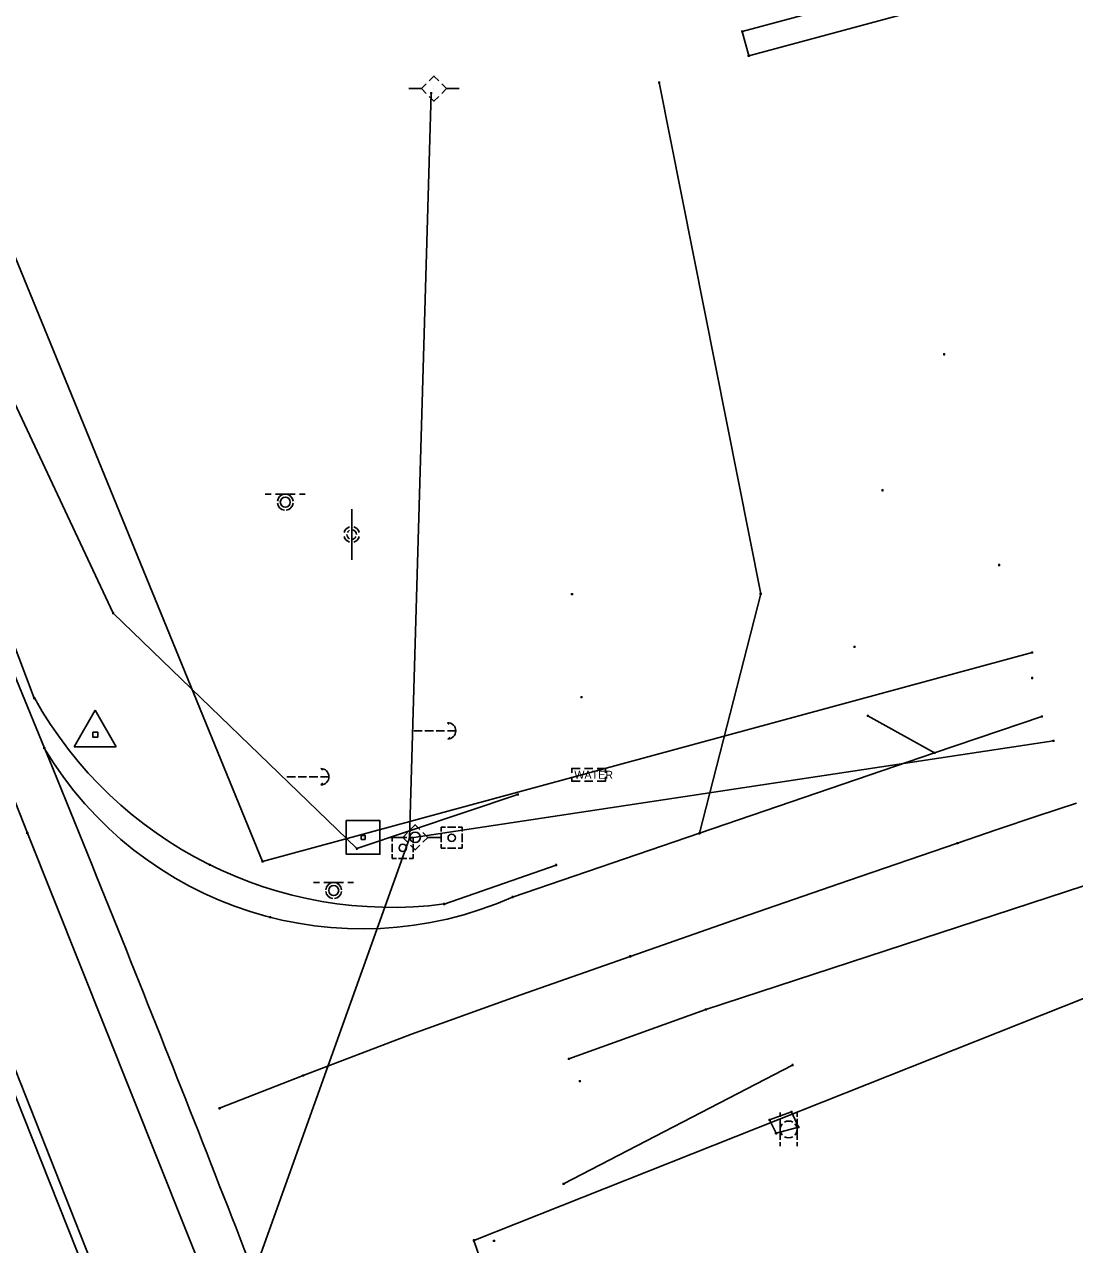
# Model space of a CAD drawing. Extents: x 1954856 to 2011933, y 399149 to 426294.
# Drawn here: x 2004670.5 to 2004795.1, y 408666 to 408810.8 of the extents above; entities that cross this region are included whole.
import ezdxf

# ---------------------------------------------------------------- set-up
doc = ezdxf.new("R2010")
doc.units = 0
for name, color, linetype in [('BankMent_ep', 7, 'Continuous'), ('BaselineSurvey', 7, 'Continuous'), ('DelineatorPost_ep', 7, 'Continuous'), ('Driveway_ep', 7, 'Continuous'), ('ElecAer_ep', 7, 'Continuous'), ('GuyWireAnchor_ep', 7, 'Continuous'), ('MeterWater_ep', 7, 'Continuous'), ('MonumentCC_ep', 7, 'Continuous'), ('MonumentNL_ep', 7, 'Continuous'), ('PavtAsphalt_ep', 7, 'Continuous'), ('PavtAsphaltCrown_ep', 7, 'Continuous'), ('PointLocator_ep', 7, 'Continuous'), ('PoleElec_ep', 7, 'Continuous'), ('PoleShared_ep', 7, 'Continuous'), ('ShldrPaved_ep', 7, 'Continuous'), ('SidewalkFront_ep', 7, 'Continuous'), ('SignSingle_ep', 7, 'Continuous'), ('TelePed_ep', 7, 'Continuous'), ('TeleServBox_ep', 7, 'Continuous'), ('TreeLineScatter_ep', 7, 'Continuous'), ('TreeLineWoods_ep', 7, 'Continuous'), ('WaterFct_ep', 7, 'Continuous')]:
    doc.layers.add(name, color=color, linetype=linetype)

msp = doc.modelspace()

# ---------------------------------------------------------------- linework, layer by layer
at = {"layer": 'BankMent_ep'}
for p, q in [((2004671.65, 408730.86), (2004641.52, 408810.02)), ((2004681, 408740.93), (2004663.38, 408778.51)), ((2004709.94, 408712.99), (2004681, 408740.93)), ((2004729.03, 408719.41), (2004709.94, 408712.99)), ((2004733.59, 408711.03), (2004720.32, 408706.41)), ((2004734.48, 408673.19), (2004761.65, 408687.3))]:
    msp.add_line(p, q, dxfattribs=at)
msp.add_arc((2004714.07, 408754.62), 48.61, 209.2548, 277.3919, dxfattribs=at)
at = {"layer": 'BaselineSurvey'}
msp.add_line((2004967.71, 407935.04), (2004043.6, 410254.04), dxfattribs=at)
msp.add_line((2004967.71, 407935.04), (2004043.6, 410254.04), dxfattribs=at)
at = {"layer": 'DelineatorPost_ep'}
for p, q in [((2004760.19, 408681.65), (2004760.19, 408681.15)), ((2004760.19, 408678.4), (2004760.19, 408680.9)), ((2004762.19, 408681.65), (2004762.19, 408681.15)), ((2004762.19, 408680.9), (2004762.19, 408678.4)), ((2004761.19, 408679.65), (2004761.19, 408679.65)), ((2004760.19, 408678.15), (2004760.19, 408677.65)), ((2004762.19, 408678.15), (2004762.19, 408677.65))]:
    msp.add_line(p, q, dxfattribs=at)
for start, end in [(60, 120), (138.5904, 221.4096), (318.5904, 41.4096), (240, 300)]:
    msp.add_arc((2004761.19, 408679.65), 1, start, end, dxfattribs=at)
at = {"layer": 'Driveway_ep'}
msp.add_line((2004778.5, 408724.36), (2004770.59, 408728.75), dxfattribs=at)
msp.add_lwpolyline([(2004750.63, 408714.8), (2004757.88, 408743.22), (2004745.83, 408803.92)], dxfattribs=at)
at = {"layer": 'ElecAer_ep'}
for points in [[(2004716.19, 408714.22), (2004718.76, 408802.67)], [(2004669.71, 408584.23), (2004716.19, 408714.22), (2004792.62, 408725.78)]]:
    msp.add_lwpolyline(points, dxfattribs=at)
at = {"layer": 'GuyWireAnchor_ep'}
for p, q in [((2004716.69, 408726.97), (2004717.69, 408726.97)), ((2004718.02, 408726.97), (2004719.02, 408726.97)), ((2004719.35, 408726.97), (2004720.35, 408726.97)), ((2004720.71, 408727.93), (2004720.91, 408727.74)), ((2004720.69, 408726.96), (2004721.69, 408726.96)), ((2004720.73, 408725.99), (2004720.97, 408726.22)), ((2004721.69, 408726.96), (2004721.69, 408726.96)), ((2004701.64, 408721.52), (2004702.64, 408721.52)), ((2004702.97, 408721.52), (2004703.97, 408721.52)), ((2004704.3, 408721.52), (2004705.3, 408721.52)), ((2004705.64, 408721.51), (2004706.64, 408721.51)), ((2004705.66, 408722.48), (2004705.86, 408722.29)), ((2004706.64, 408721.51), (2004706.64, 408721.51)), ((2004705.68, 408720.54), (2004705.92, 408720.77))]:
    msp.add_line(p, q, dxfattribs=at)
for centre in [(2004720.71, 408726.96), (2004705.66, 408721.51)]:
    msp.add_arc(centre, 0.973, 271.14, 90.0059, dxfattribs=at)
at = {"layer": 'MeterWater_ep'}
msp.add_line((2004737.45, 408721.74), (2004737.45, 408721.74), dxfattribs=at)
for points in [[(2004735.45, 408721.99), (2004735.45, 408722.5), (2004736.45, 408722.5)], [(2004736.45, 408720.99), (2004735.45, 408720.99), (2004735.45, 408721.49)], [(2004736.95, 408722.5), (2004737.95, 408722.5)], [(2004738.45, 408722.5), (2004739.45, 408722.5), (2004739.45, 408721.99)], [(2004739.45, 408721.49), (2004739.45, 408720.99), (2004738.45, 408720.99)], [(2004737.95, 408720.99), (2004736.95, 408720.99)]]:
    msp.add_lwpolyline(points, dxfattribs=at)
at = {"layer": 'MonumentCC_ep'}
msp.add_line((2004710.68, 408714.32), (2004710.68, 408714.32), dxfattribs=at)
msp.add_lwpolyline([(2004708.68, 408712.32), (2004712.68, 408712.32), (2004712.68, 408716.32), (2004708.68, 408716.32), (2004708.68, 408712.32)], dxfattribs=at)
msp.add_lwpolyline([(2004710.44, 408714.08), (2004710.44, 408714.55), (2004710.92, 408714.55), (2004710.92, 408714.08)], close=True, dxfattribs=at)
at = {"layer": 'MonumentNL_ep'}
for p, q in [((2004676.39, 408725.08), (2004678.89, 408729.41)), ((2004678.89, 408729.41), (2004681.39, 408725.08)), ((2004678.89, 408726.52), (2004678.89, 408726.52)), ((2004676.39, 408725.08), (2004681.39, 408725.08))]:
    msp.add_line(p, q, dxfattribs=at)
msp.add_lwpolyline([(2004678.59, 408726.82), (2004679.19, 408726.82), (2004679.19, 408726.22), (2004678.59, 408726.22)], close=True, dxfattribs=at)
at = {"layer": 'PavtAsphalt_ep'}
for p, q in [((2004791.24, 408728.67), (2004778.5, 408724.36)), ((2004778.5, 408724.36), (2004750.63, 408714.8)), ((2004750.63, 408714.8), (2004728.42, 408707.24)), ((2004751.37, 408693.88), (2004798.39, 408709.27)), ((2004735.11, 408688.04), (2004751.37, 408693.88))]:
    msp.add_line(p, q, dxfattribs=at)
msp.add_lwpolyline([(2004930.29, 408065.1), (2004893.54, 408157.67), (2004856.38, 408250.56), (2004819.21, 408343.48), (2004782.13, 408435.87), (2004745.09, 408528.98), (2004708.04, 408621.61), (2004670.84, 408714.83), (2004634.43, 408807.2), (2004597.18, 408900.11), (2004560.23, 408993.39), (2004523.08, 409086.65), (2004486.25, 409179.55), (2004449.35, 409272.32), (2004412.41, 409364.96), (2004375.27, 409458.2), (2004338.19, 409550.48), (2004300.95, 409644.08)], dxfattribs=at)
msp.add_arc((2004710.6, 408747.41), 43.95, 210.7909, 293.9313, dxfattribs=at)
at = {"layer": 'PavtAsphaltCrown_ep'}
msp.add_line((2004693.65, 408682.16), (2004703.56, 408686.05), dxfattribs=at)
for points in [[(2004919.3, 408060.52), (2004882.31, 408153.48), (2004845.12, 408246.24), (2004807.96, 408339.12), (2004770.74, 408431.91), (2004733.82, 408525.03), (2004696.73, 408617.52), (2004659.9, 408710.76), (2004622.5, 408803.47), (2004585.74, 408896.22), (2004548.97, 408989.35), (2004511.74, 409082.34), (2004474.91, 409175.32), (2004437.75, 409268.1), (2004401.04, 409361.08), (2004363.75, 409453.88), (2004326.65, 409546.7), (2004289.56, 409639.69)], [(2004703.56, 408686.05), (2004716.44, 408690.95), (2004729.4, 408695.63), (2004742.4, 408700.19), (2004755.34, 408704.71), (2004768.29, 408709.2), (2004781.25, 408713.65), (2004785.95, 408715.24), (2004790.65, 408716.82), (2004795.35, 408718.4)]]:
    msp.add_lwpolyline(points, dxfattribs=at)
at = {"layer": 'PointLocator_ep'}
for p, q in [((2004755.82, 408809.99), (2004755.57, 408809.99)), ((2004755.69, 408809.86), (2004755.69, 408810.11)), ((2004755.69, 408809.99), (2004755.69, 408809.99)), ((2004756.57, 408807.11), (2004756.32, 408807.11)), ((2004756.45, 408806.99), (2004756.45, 408807.24)), ((2004756.45, 408807.11), (2004756.45, 408807.11)), ((2004745.95, 408803.92), (2004745.7, 408803.92)), ((2004745.83, 408803.79), (2004745.83, 408804.04)), ((2004745.83, 408803.92), (2004745.83, 408803.92)), ((2004718.89, 408802.67), (2004718.64, 408802.67)), ((2004718.76, 408802.54), (2004718.76, 408802.79)), ((2004718.76, 408802.67), (2004718.76, 408802.67)), ((2004779.79, 408771.66), (2004779.54, 408771.66)), ((2004779.66, 408771.53), (2004779.66, 408771.78)), ((2004779.66, 408771.66), (2004779.66, 408771.66)), ((2004772.45, 408755.52), (2004772.2, 408755.52)), ((2004772.32, 408755.39), (2004772.32, 408755.64)), ((2004772.32, 408755.52), (2004772.32, 408755.52)), ((2004786.31, 408746.65), (2004786.06, 408746.65)), ((2004786.18, 408746.53), (2004786.18, 408746.78)), ((2004786.18, 408746.65), (2004786.18, 408746.65)), ((2004735.6, 408743.18), (2004735.35, 408743.18)), ((2004735.48, 408743.06), (2004735.48, 408743.31)), ((2004735.48, 408743.18), (2004735.48, 408743.18)), ((2004758, 408743.22), (2004757.75, 408743.22)), ((2004757.88, 408743.1), (2004757.88, 408743.35)), ((2004757.88, 408743.22), (2004757.88, 408743.22)), ((2004681.13, 408740.93), (2004680.88, 408740.93)), ((2004681, 408740.8), (2004681, 408741.05)), ((2004681, 408740.93), (2004681, 408740.93)), ((2004769.13, 408736.92), (2004768.88, 408736.92)), ((2004769, 408736.8), (2004769, 408737.05)), ((2004769, 408736.92), (2004769, 408736.92)), ((2004790.22, 408736.27), (2004789.97, 408736.27)), ((2004790.09, 408736.14), (2004790.09, 408736.39)), ((2004790.09, 408736.27), (2004790.09, 408736.27)), ((2004790.21, 408733.23), (2004789.96, 408733.23)), ((2004790.09, 408733.11), (2004790.09, 408733.36)), ((2004790.09, 408733.23), (2004790.09, 408733.23)), ((2004671.78, 408730.86), (2004671.53, 408730.86)), ((2004671.65, 408730.74), (2004671.65, 408730.99)), ((2004671.65, 408730.86), (2004671.65, 408730.86)), ((2004736.73, 408730.96), (2004736.48, 408730.96)), ((2004736.61, 408730.83), (2004736.61, 408731.08)), ((2004736.61, 408730.96), (2004736.61, 408730.96)), ((2004770.72, 408728.75), (2004770.47, 408728.75)), ((2004770.59, 408728.62), (2004770.59, 408728.87)), ((2004770.59, 408728.75), (2004770.59, 408728.75)), ((2004791.36, 408728.67), (2004791.11, 408728.67)), ((2004791.24, 408728.54), (2004791.24, 408728.79)), ((2004791.24, 408728.67), (2004791.24, 408728.67)), ((2004792.74, 408725.78), (2004792.49, 408725.78)), ((2004792.62, 408725.66), (2004792.62, 408725.91)), ((2004792.62, 408725.78), (2004792.62, 408725.78)), ((2004672.97, 408724.92), (2004672.72, 408724.92)), ((2004672.85, 408724.79), (2004672.85, 408725.04)), ((2004672.85, 408724.92), (2004672.85, 408724.92)), ((2004778.62, 408724.36), (2004778.37, 408724.36)), ((2004778.5, 408724.24), (2004778.5, 408724.49)), ((2004778.5, 408724.36), (2004778.5, 408724.36)), ((2004729.16, 408719.41), (2004728.91, 408719.41)), ((2004729.03, 408719.28), (2004729.03, 408719.53)), ((2004729.03, 408719.41), (2004729.03, 408719.41)), ((2004670.96, 408714.83), (2004670.71, 408714.83)), ((2004670.84, 408714.71), (2004670.84, 408714.96)), ((2004670.84, 408714.83), (2004670.84, 408714.83)), ((2004716.31, 408714.22), (2004716.06, 408714.22)), ((2004716.19, 408714.09), (2004716.19, 408714.34)), ((2004716.19, 408714.22), (2004716.19, 408714.22)), ((2004750.76, 408714.8), (2004750.51, 408714.8)), ((2004750.63, 408714.68), (2004750.63, 408714.93)), ((2004750.63, 408714.8), (2004750.63, 408714.8)), ((2004710.06, 408712.99), (2004709.81, 408712.99)), ((2004709.94, 408712.86), (2004709.94, 408713.11)), ((2004709.94, 408712.99), (2004709.94, 408712.99)), ((2004781.38, 408713.65), (2004781.13, 408713.65)), ((2004781.25, 408713.52), (2004781.25, 408713.77)), ((2004781.25, 408713.65), (2004781.25, 408713.65)), ((2004692.61, 408711.06), (2004692.36, 408711.06)), ((2004692.49, 408710.93), (2004692.49, 408711.18)), ((2004692.49, 408711.06), (2004692.49, 408711.06)), ((2004698.89, 408711.47), (2004698.64, 408711.47)), ((2004698.76, 408711.34), (2004698.76, 408711.59)), ((2004698.76, 408711.47), (2004698.76, 408711.47)), ((2004733.59, 408710.91), (2004733.59, 408711.16)), ((2004733.72, 408711.03), (2004733.47, 408711.03)), ((2004733.59, 408711.03), (2004733.59, 408711.03)), ((2004728.55, 408707.24), (2004728.3, 408707.24)), ((2004728.42, 408707.12), (2004728.42, 408707.37)), ((2004728.42, 408707.24), (2004728.42, 408707.24)), ((2004720.45, 408706.41), (2004720.2, 408706.41)), ((2004720.32, 408706.29), (2004720.32, 408706.54)), ((2004720.32, 408706.41), (2004720.32, 408706.41)), ((2004699.78, 408704.85), (2004699.53, 408704.85)), ((2004699.66, 408704.73), (2004699.66, 408704.98)), ((2004699.66, 408704.85), (2004699.66, 408704.85)), ((2004742.53, 408700.19), (2004742.28, 408700.19)), ((2004742.4, 408700.07), (2004742.4, 408700.32)), ((2004742.4, 408700.19), (2004742.4, 408700.19)), ((2004751.49, 408693.88), (2004751.24, 408693.88)), ((2004751.37, 408693.76), (2004751.37, 408694.01)), ((2004751.37, 408693.88), (2004751.37, 408693.88)), ((2004735.24, 408688.04), (2004734.99, 408688.04)), ((2004735.11, 408687.91), (2004735.11, 408688.16)), ((2004735.11, 408688.04), (2004735.11, 408688.04)), ((2004761.78, 408687.3), (2004761.53, 408687.3)), ((2004761.65, 408687.17), (2004761.65, 408687.42)), ((2004761.65, 408687.3), (2004761.65, 408687.3)), ((2004703.69, 408686.05), (2004703.44, 408686.05)), ((2004703.56, 408685.93), (2004703.56, 408686.18)), ((2004703.56, 408686.05), (2004703.56, 408686.05)), ((2004736.54, 408685.37), (2004736.29, 408685.37)), ((2004736.42, 408685.25), (2004736.42, 408685.5)), ((2004736.42, 408685.37), (2004736.42, 408685.37)), ((2004693.78, 408682.16), (2004693.53, 408682.16)), ((2004693.65, 408682.03), (2004693.65, 408682.28)), ((2004693.65, 408682.16), (2004693.65, 408682.16)), ((2004759.07, 408680.8), (2004758.82, 408680.8)), ((2004758.94, 408680.68), (2004758.94, 408680.93)), ((2004758.94, 408680.8), (2004758.94, 408680.8)), ((2004761.67, 408681.74), (2004761.42, 408681.74)), ((2004761.55, 408681.61), (2004761.55, 408681.86)), ((2004761.55, 408681.74), (2004761.55, 408681.74)), ((2004759.82, 408679.19), (2004759.57, 408679.19)), ((2004759.7, 408679.07), (2004759.7, 408679.32)), ((2004759.7, 408679.19), (2004759.7, 408679.19)), ((2004762.47, 408679.92), (2004762.22, 408679.92)), ((2004762.35, 408679.79), (2004762.35, 408680.04)), ((2004762.35, 408679.92), (2004762.35, 408679.92)), ((2004734.61, 408673.19), (2004734.36, 408673.19)), ((2004734.48, 408673.06), (2004734.48, 408673.31)), ((2004734.48, 408673.19), (2004734.48, 408673.19)), ((2004723.94, 408666.48), (2004723.69, 408666.48)), ((2004723.81, 408666.36), (2004723.81, 408666.61)), ((2004723.81, 408666.48), (2004723.81, 408666.48)), ((2004726.35, 408666.42), (2004726.1, 408666.42)), ((2004726.23, 408666.3), (2004726.23, 408666.55)), ((2004726.23, 408666.42), (2004726.23, 408666.42))]:
    msp.add_line(p, q, dxfattribs=at)
at = {"layer": 'PoleElec_ep'}
for p, q in [((2004717.61, 408803.2), (2004718.17, 408803.76)), ((2004716.11, 408803.2), (2004717.61, 408803.2)), ((2004718.17, 408802.63), (2004717.61, 408803.2)), ((2004719.09, 408803.2), (2004719.09, 408803.2)), ((2004722.08, 408803.2), (2004720.58, 408803.2))]:
    msp.add_line(p, q, dxfattribs=at)
for points in [[(2004718.53, 408804.12), (2004719.09, 408804.68), (2004719.66, 408804.12)], [(2004720.01, 408803.76), (2004720.58, 408803.2), (2004720.01, 408802.63)], [(2004719.66, 408802.28), (2004719.09, 408801.71), (2004718.53, 408802.28)]]:
    msp.add_lwpolyline(points, dxfattribs=at)
at = {"layer": 'PoleShared_ep'}
for p, q in [((2004713.88, 408714.32), (2004715.38, 408714.32)), ((2004715.38, 408714.32), (2004715.94, 408714.89)), ((2004715.94, 408713.76), (2004715.38, 408714.32)), ((2004716.86, 408714.32), (2004716.86, 408714.32)), ((2004719.85, 408714.32), (2004718.35, 408714.32))]:
    msp.add_line(p, q, dxfattribs=at)
for points in [[(2004716.3, 408715.25), (2004716.86, 408715.81), (2004717.43, 408715.24)], [(2004717.79, 408714.89), (2004718.35, 408714.32), (2004717.79, 408713.76)], [(2004717.43, 408713.4), (2004716.86, 408712.83), (2004716.3, 408713.4)]]:
    msp.add_lwpolyline(points, dxfattribs=at)
for start, end in [(90, 270), (270, 90)]:
    msp.add_arc((2004716.86, 408714.32), 0.625, start, end, dxfattribs=at)
at = {"layer": 'ShldrPaved_ep'}
msp.add_line((2004672.85, 408724.92), (2004638.42, 408808.92), dxfattribs=at)
msp.add_arc((2001517.39, 407431.8), 3410.15, 20.81865, 22.28405, dxfattribs=at)
at = {"layer": 'SidewalkFront_ep'}
msp.add_lwpolyline([(2004771.33, 408815.36), (2004771.64, 408814.29), (2004755.69, 408809.99), (2004756.45, 408807.11), (2004794.96, 408817.49), (2004794.09, 408820.37), (2004778.18, 408816.1), (2004777.91, 408817.14)], dxfattribs=at)
at = {"layer": 'SignSingle_ep'}
for p, q in [((2004699.07, 408755.07), (2004699.77, 408755.07)), ((2004700.27, 408755.07), (2004702.62, 408755.07)), ((2004703.12, 408755.07), (2004703.82, 408755.07)), ((2004701.45, 408754.11), (2004701.45, 408754.11)), ((2004704.81, 408708.96), (2004705.51, 408708.96)), ((2004706.01, 408708.96), (2004708.36, 408708.96)), ((2004708.86, 408708.96), (2004709.56, 408708.96)), ((2004707.19, 408708.01), (2004707.19, 408708.01))]:
    msp.add_line(p, q, dxfattribs=at)
for centre in [(2004701.45, 408754.11), (2004707.19, 408708.01)]:
    msp.add_circle(centre, 0.594, dxfattribs=at)
for centre, start, end in [((2004701.45, 408754.11), 96.0423, 173.9577), ((2004701.45, 408754.11), 6.0423, 83.9577), ((2004701.45, 408754.11), 186.0423, 263.9577), ((2004701.45, 408754.11), 276.0423, 353.9577), ((2004707.19, 408708.01), 96.0423, 173.9577), ((2004707.19, 408708.01), 6.0423, 83.9577), ((2004707.19, 408708.01), 186.0423, 263.9577), ((2004707.19, 408708.01), 276.0423, 353.9577)]:
    msp.add_arc(centre, 0.95, start, end, dxfattribs=at)
at = {"layer": 'TelePed_ep'}
for p, q in [((2004719.95, 408715.52), (2004720.45, 408715.52)), ((2004719.95, 408715.02), (2004719.95, 408715.52)), ((2004720.7, 408715.52), (2004721.7, 408715.52)), ((2004721.95, 408715.52), (2004722.45, 408715.52)), ((2004722.45, 408715.02), (2004722.45, 408715.52)), ((2004714.14, 408714.32), (2004714.64, 408714.32)), ((2004714.14, 408713.82), (2004714.14, 408714.32)), ((2004714.89, 408714.32), (2004715.89, 408714.32)), ((2004716.14, 408714.32), (2004716.64, 408714.32)), ((2004716.64, 408713.82), (2004716.64, 408714.32)), ((2004719.95, 408713.77), (2004719.95, 408714.77)), ((2004721.2, 408714.27), (2004721.2, 408714.27)), ((2004722.45, 408713.77), (2004722.45, 408714.77)), ((2004714.14, 408712.57), (2004714.14, 408713.57)), ((2004715.39, 408713.07), (2004715.39, 408713.07)), ((2004716.64, 408712.57), (2004716.64, 408713.57)), ((2004719.95, 408713.02), (2004719.95, 408713.52)), ((2004720.45, 408713.02), (2004719.95, 408713.02)), ((2004721.7, 408713.02), (2004720.7, 408713.02)), ((2004722.45, 408713.02), (2004721.95, 408713.02)), ((2004722.45, 408713.02), (2004722.45, 408713.52)), ((2004714.14, 408711.82), (2004714.14, 408712.32)), ((2004714.64, 408711.82), (2004714.14, 408711.82)), ((2004715.89, 408711.82), (2004714.89, 408711.82)), ((2004716.64, 408711.82), (2004716.14, 408711.82)), ((2004716.64, 408711.82), (2004716.64, 408712.32))]:
    msp.add_line(p, q, dxfattribs=at)
for centre in [(2004721.2, 408714.27), (2004715.39, 408713.07)]:
    msp.add_circle(centre, 0.438, dxfattribs=at)
at = {"layer": 'TeleServBox_ep'}
msp.add_lwpolyline([(2004758.94, 408680.8), (2004759.7, 408679.19), (2004762.35, 408679.92), (2004761.55, 408681.74)], close=True, dxfattribs=at)
at = {"layer": 'TreeLineScatter_ep'}
msp.add_lwpolyline([(2004790.09, 408736.27), (2004698.76, 408711.47), (2004581.18, 408998.73)], dxfattribs=at)
at = {"layer": 'TreeLineWoods_ep'}
msp.add_lwpolyline([(2004962.08, 408264.45), (2004889.22, 408234.95), (2004880.19, 408259.78), (2004843.8, 408353.14), (2004808.8, 408445.58), (2004768.25, 408537.94), (2004723.81, 408666.48), (2004801.59, 408697.32)], dxfattribs=at)
at = {"layer": 'WaterFct_ep'}
for p, q in [((2004709.33, 408753.27), (2004709.33, 408747.27)), ((2004709.33, 408750.27), (2004709.33, 408750.27))]:
    msp.add_line(p, q, dxfattribs=at)
for radius, start, end in [(0.937, 105.466, 164.534), (0.562, 180, 243.6122), (0.562, 116.3878, 153.6122), (0.562, 0, 90), (0.937, 15.466, 74.534), (0.937, 195.466, 254.534), (0.562, 270, 333.6122), (0.937, 285.466, 344.534)]:
    msp.add_arc((2004709.33, 408750.27), radius, start, end, dxfattribs=at)

# ---------------------------------------------------------------- texts
at = {"layer": 'MeterWater_ep'}
msp.add_text('WATER', height=0.95, dxfattribs=at).set_placement((2004735.76, 408721.27))

doc.saveas('drawing.dxf')
